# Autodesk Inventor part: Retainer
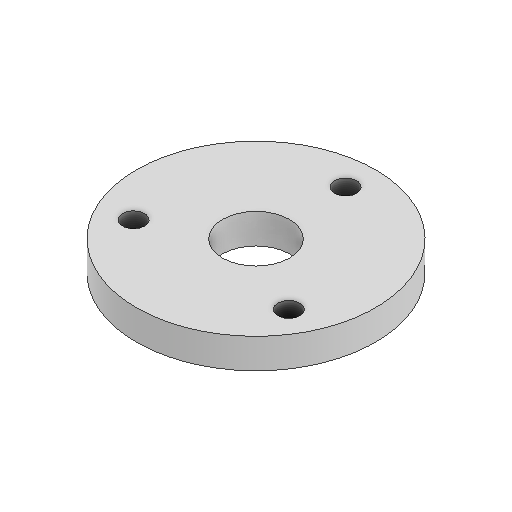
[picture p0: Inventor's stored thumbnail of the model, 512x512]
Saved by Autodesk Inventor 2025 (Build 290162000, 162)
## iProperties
Created: 2019-03
Part Number: Retainer
Material: Generic
Document SubType Name: Modeling
Designer: LENOVO-CADCIM
Density: 1 g/cm^3
Appearance: Default
Author: LENOVO-CADCIM
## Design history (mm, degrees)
sketch "Sketch1" dims "d1" = 150
  geometry: C1 r 100 at (0, 0); 3 further points
  constraints: 2 coincident, 1 centre point, 1 vertical alignment, 2 other
  dimensions: "d0" = 200 diameter of C1
extrude "Extrusion1" new body sketch "Sketch1" stored distance "d2" = 25; taper "d3" = 0 deg
sketch "Sketch2" dims "d4" = 150
  geometry: 3 further points
  constraints: 1 coincident, 1 vertical alignment, 2 other
hole "Hole1" sketch "Sketch2" at (0, 75) diameter "d5" = 18.376; stored, may be unused: countersink angle "d9" = 90 deg, drill point angle "d11" = 118 deg; dims "d6" = 40, "d7" = 4.4, "d8" = 2, "d10" = 47.3
pattern_circular "Circular Pattern1" dims angle "d13" = 360 deg
sketch "Sketch3"
  geometry: C1 r 28 at (0, 0); 1 further point
  constraints: 1 centre point, 1 coincident
  dimensions: "d15" = 56 diameter of C1
extrude "Extrusion2" cut sketch "Sketch3" distance "d16" = 25; taper "d17" = 0 deg
body "Solid1"
